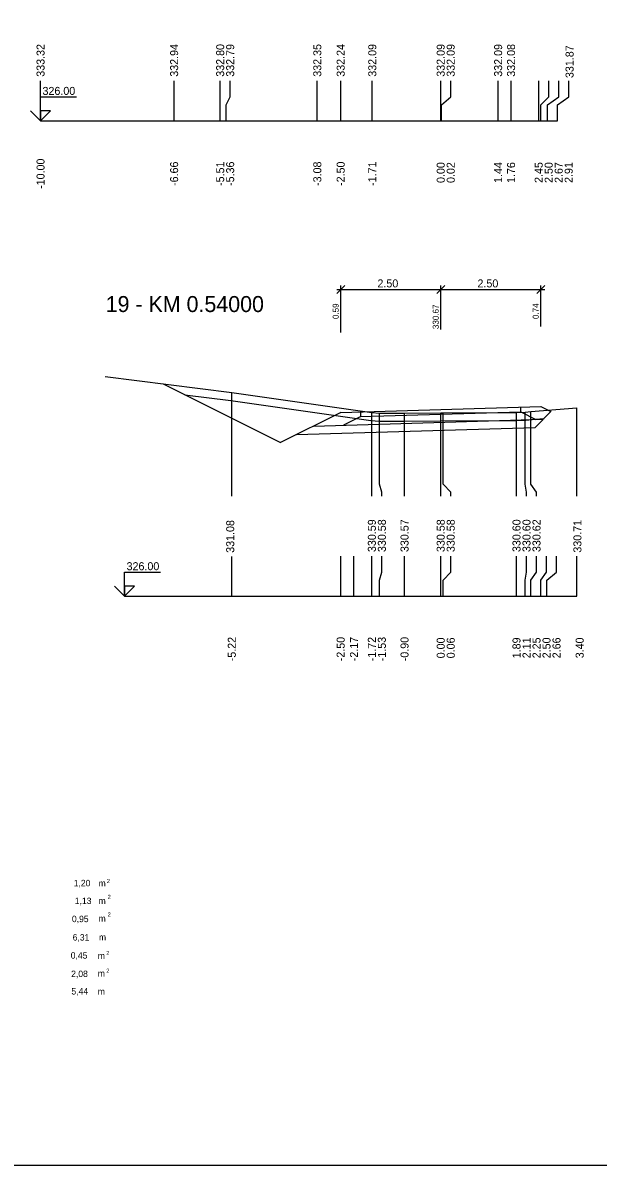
# Model space of a CAD drawing. Extents: x 1989 to 2511, y -2653 to -2294.
# Drawn here: x 2046.5 to 2060.88, y -2360.13 to -2331.57 of the extents above; entities that cross this region are included whole.
import ezdxf

# ---------------------------------------------------------------- set-up
doc = ezdxf.new("R2010")
doc.units = 0
for name, color, linetype in [('KOTA', 7, 'Continuous'), ('KOTA_DELKY', 7, 'Continuous'), ('KOTA_DELKY_CONT', 7, 'Continuous'), ('REZY_PF_PUVODNI', 7, 'Continuous'), ('SESTAVY_REZU_PF', 7, 'Continuous'), ('SVK', 7, 'Continuous'), ('u_kubatury', 7, 'Continuous'), ('u_sejmuti', 7, 'Continuous'), ('vzorák', 7, 'Continuous'), ('x_rozpiska', 7, 'Continuous')]:
    doc.layers.add(name, color=color, linetype=linetype)

msp = doc.modelspace()

# ---------------------------------------------------------------- linework, layer by layer
at = {"layer": 'KOTA'}
for points in [[(2046.941, -2334.022), (2046.691, -2333.772), (2046.941, -2334.022), (2046.941, -2333.422), (2047.841, -2333.422)], [(2046.941, -2334.022), (2047.191, -2333.772), (2046.941, -2333.772), (2046.941, -2334.022)], [(2046.941, -2334.022), (2047.191, -2333.772), (2046.941, -2333.772)], [(2049.042, -2345.904), (2048.792, -2345.654), (2049.042, -2345.904), (2049.042, -2345.304), (2049.942, -2345.304)], [(2049.042, -2345.904), (2049.292, -2345.654), (2049.042, -2345.654), (2049.042, -2345.904)], [(2049.042, -2345.904), (2049.292, -2345.654), (2049.042, -2345.654)]]:
    msp.add_lwpolyline(points, dxfattribs=at)
at = {"layer": 'KOTA_DELKY'}
for points in [[(2054.341, -2338.334), (2054.541, -2338.134)], [(2054.341, -2338.234), (2057.041, -2338.234)], [(2054.441, -2339.309), (2054.441, -2338.134)], [(2056.841, -2338.334), (2057.041, -2338.134)], [(2056.841, -2338.334), (2057.041, -2338.134)], [(2056.841, -2338.234), (2059.541, -2338.234)], [(2056.941, -2339.234), (2056.941, -2338.134)], [(2056.941, -2339.234), (2056.941, -2338.134)], [(2059.341, -2338.334), (2059.541, -2338.134)], [(2059.441, -2339.159), (2059.441, -2338.134)]]:
    msp.add_lwpolyline(points, dxfattribs=at)
at = {"layer": 'REZY_PF_PUVODNI'}
for points in [[(2048.555, -2340.413), (2051.72, -2340.815), (2055.22, -2341.315)], [(2055.22, -2341.315), (2055.41, -2341.327), (2056.037, -2341.329), (2056.941, -2341.322), (2056.941, -2341.322), (2057, -2341.322), (2058.835, -2341.308), (2059.053, -2341.305), (2059.189, -2341.284)]]:
    msp.add_lwpolyline(points, dxfattribs=at)
at = {"layer": 'SESTAVY_REZU_PF'}
msp.add_line((2059.189, -2341.284), (2060.341, -2341.194), dxfattribs=at)
for points in [[(2046.941, -2334.022), (2059.856, -2334.022)], [(2049.042, -2345.904), (2060.341, -2345.904)]]:
    msp.add_lwpolyline(points, dxfattribs=at)
at = {"layer": 'SVK'}
for p, q in [((2060.341, -2343.404), (2060.341, -2341.194)), ((2060.341, -2345.904), (2060.341, -2344.904))]:
    msp.add_line(p, q, dxfattribs=at)
for points in [[(2046.941, -2334.022), (2046.941, -2333.022)], [(2046.941, -2334.022), (2046.941, -2333.022)], [(2050.279, -2334.022), (2050.279, -2333.022)], [(2051.43, -2334.022), (2051.43, -2333.022)], [(2051.581, -2334.022), (2051.581, -2333.622), (2051.68, -2333.422), (2051.68, -2333.022)], [(2053.857, -2334.022), (2053.857, -2333.022)], [(2054.441, -2334.022), (2054.441, -2333.022)], [(2055.231, -2334.022), (2055.231, -2333.022)], [(2056.941, -2334.022), (2056.941, -2333.022)], [(2056.96, -2334.022), (2056.96, -2333.622), (2057.191, -2333.422), (2057.191, -2333.022)], [(2058.376, -2334.022), (2058.376, -2333.022)], [(2058.699, -2334.022), (2058.699, -2333.022)], [(2059.389, -2334.022), (2059.389, -2333.022)], [(2059.441, -2334.022), (2059.441, -2333.622), (2059.639, -2333.422), (2059.639, -2333.022)], [(2059.613, -2334.022), (2059.613, -2333.622), (2059.889, -2333.422), (2059.889, -2333.022)], [(2059.856, -2334.022), (2059.856, -2333.622), (2060.139, -2333.422), (2060.139, -2333.022)], [(2051.72, -2343.405), (2051.72, -2340.815)], [(2055.22, -2343.404), (2055.22, -2341.315)], [(2055.47, -2343.404), (2055.47, -2343.304), (2055.41, -2343.104), (2055.41, -2341.327)], [(2056.037, -2343.404), (2056.037, -2341.329)], [(2056.941, -2343.404), (2056.941, -2341.322)], [(2057.191, -2343.404), (2057.191, -2343.304), (2057, -2343.104), (2057, -2341.322)], [(2058.835, -2343.404), (2058.835, -2341.308)], [(2059.085, -2343.404), (2059.085, -2343.304), (2059.053, -2343.104), (2059.053, -2341.305)], [(2059.335, -2343.404), (2059.335, -2343.304), (2059.189, -2343.104), (2059.189, -2341.284)], [(2051.72, -2345.904), (2051.72, -2344.912)], [(2054.441, -2345.904), (2054.441, -2344.904)], [(2054.774, -2345.904), (2054.774, -2344.904)], [(2055.22, -2345.904), (2055.22, -2344.904)], [(2055.41, -2345.904), (2055.41, -2345.504), (2055.47, -2345.304), (2055.47, -2344.904)], [(2056.037, -2345.904), (2056.037, -2344.904)], [(2056.941, -2345.904), (2056.941, -2344.904)], [(2057, -2345.904), (2057, -2345.504), (2057.191, -2345.304), (2057.191, -2344.904)], [(2058.835, -2345.904), (2058.835, -2344.904)], [(2059.053, -2345.904), (2059.053, -2345.504), (2059.085, -2345.304), (2059.085, -2344.904)], [(2059.189, -2345.904), (2059.189, -2345.504), (2059.335, -2345.304), (2059.335, -2344.904)], [(2059.441, -2345.904), (2059.441, -2345.504), (2059.585, -2345.304), (2059.585, -2344.904)], [(2059.596, -2345.904), (2059.596, -2345.504), (2059.835, -2345.304), (2059.835, -2344.904)]]:
    msp.add_lwpolyline(points, dxfattribs=at)
at = {"layer": 'u_sejmuti'}
msp.add_line((2059.205, -2341.483), (2059.523, -2341.459), dxfattribs=at)
for points in [[(2050.544, -2340.867), (2051.693, -2341.014), (2055.192, -2341.513)], [(2055.207, -2341.515), (2055.403, -2341.527), (2056.037, -2341.529), (2056.942, -2341.522), (2058.837, -2341.508), (2059.069, -2341.505), (2059.219, -2341.482)]]:
    msp.add_lwpolyline(points, dxfattribs=at)
at = {"layer": 'vzorák'}
for p, q in [((2050.003, -2340.597), (2052.934, -2342.062)), ((2054.441, -2341.309), (2059.441, -2341.159)), ((2058.941, -2341.294), (2058.941, -2341.174)), ((2059.441, -2341.159), (2059.695, -2341.286)), ((2054.441, -2341.309), (2052.934, -2342.062)), ((2053.759, -2341.649), (2059.504, -2341.477)), ((2054.941, -2341.414), (2054.515, -2341.627)), ((2054.941, -2341.414), (2058.941, -2341.294)), ((2054.941, -2341.414), (2054.941, -2341.294)), ((2058.941, -2341.294), (2059.318, -2341.483)), ((2059.298, -2341.683), (2059.695, -2341.286)), ((2053.334, -2341.862), (2059.298, -2341.683))]:
    msp.add_line(p, q, dxfattribs=at)
at = {"layer": 'x_rozpiska'}
msp.add_lwpolyline([(2078.309, -2300.726), (1994.309, -2300.726), (1994.309, -2360.126), (2078.309, -2360.126)], close=True, dxfattribs=at)

# ---------------------------------------------------------------- texts
at = {"layer": 'KOTA'}
for p in [(2046.99, -2333.372), (2049.091, -2345.254)]:
    msp.add_text('326.00', height=0.2, dxfattribs=at).set_placement(p)
at = {"layer": 'KOTA_DELKY'}
for p in [(2055.36, -2338.184), (2057.86, -2338.184)]:
    msp.add_text('2.50', height=0.2, dxfattribs=at).set_placement(p)
at = {"layer": 'KOTA_DELKY_CONT'}
for s, p in [('0.59', (2054.391, -2338.975)), ('330.67', (2056.891, -2339.226)), ('0.74', (2059.391, -2338.975))]:
    msp.add_text(s, height=0.15, rotation=90, dxfattribs=at).set_placement(p)
at = {"layer": 'SESTAVY_REZU_PF'}
msp.add_text('19 - KM 0.54000', height=0.4, dxfattribs=at).set_placement((2048.569, -2338.8))
at = {"layer": 'SVK'}
for s, p in [(' 333.32', (2047.041, -2332.992)), (' 332.94', (2050.379, -2332.992)), (' 332.80', (2051.53, -2332.992)), (' 332.79', (2051.78, -2332.992)), (' 332.35', (2053.957, -2332.992)), (' 332.24', (2054.541, -2332.992)), (' 332.09', (2055.331, -2332.992)), (' 332.09', (2057.041, -2332.992)), (' 332.09', (2057.291, -2332.992)), (' 332.09', (2058.476, -2332.992)), (' 332.08', (2058.799, -2332.992)), (' 331.87', (2060.261, -2333.025)), ('-10.00', (2047.041, -2335.722)), (' -6.66', (2050.379, -2335.722)), (' -5.51', (2051.53, -2335.722)), (' -5.36', (2051.78, -2335.722)), (' -3.08', (2053.957, -2335.722)), (' -2.50', (2054.541, -2335.722)), (' -1.71', (2055.331, -2335.722)), ('  0.00', (2057.041, -2335.722)), ('  0.02', (2057.291, -2335.722)), ('  1.44', (2058.476, -2335.722)), ('  1.76', (2058.799, -2335.722)), ('  2.45', (2059.489, -2335.722)), ('  2.50', (2059.739, -2335.722)), ('  2.67', (2059.989, -2335.722)), ('  2.91', (2060.239, -2335.722)), (' 331.08', (2051.781, -2344.893)), (' 330.59', (2055.32, -2344.874)), (' 330.58', (2055.57, -2344.874)), (' 330.57', (2056.137, -2344.874)), (' 330.58', (2057.041, -2344.874)), (' 330.58', (2057.291, -2344.874)), (' 330.60', (2058.935, -2344.874)), (' 330.60', (2059.185, -2344.874)), (' 330.62', (2059.435, -2344.874)), (' 330.71', (2060.457, -2344.889)), (' -5.22', (2051.82, -2347.604)), (' -2.50', (2054.541, -2347.604)), (' -2.17', (2054.874, -2347.604)), (' -1.72', (2055.32, -2347.604)), (' -1.53', (2055.57, -2347.604)), (' -0.90', (2056.137, -2347.604)), ('  0.00', (2057.041, -2347.604)), ('  0.06', (2057.291, -2347.604)), ('  1.89', (2058.935, -2347.604)), ('  2.11', (2059.185, -2347.604)), ('  2.25', (2059.435, -2347.604)), ('  2.50', (2059.685, -2347.604)), ('  2.66', (2059.935, -2347.604)), ('  3.40', (2060.513, -2347.604))]:
    msp.add_text(s, height=0.2, rotation=90, dxfattribs=at).set_placement(p)
at = {"layer": 'u_kubatury'}
for s, height, p in [('2', 0.104, (2048.595, -2353.075)), ('1,20', 0.16, (2047.77, -2353.154)), ('m', 0.16, (2048.392, -2353.159)), ('1,13', 0.16, (2047.797, -2353.599)), ('m', 0.16, (2048.392, -2353.596)), ('2', 0.104, (2048.617, -2353.472)), ('2', 0.104, (2048.617, -2353.914)), ('0,95', 0.16, (2047.725, -2354.051)), ('m', 0.16, (2048.392, -2354.039)), ('6,31', 0.16, (2047.744, -2354.511)), ('m', 0.16, (2048.4, -2354.508)), ('0,45', 0.16, (2047.695, -2354.963)), ('m', 0.16, (2048.371, -2354.969)), ('2', 0.104, (2048.582, -2354.876)), ('2', 0.104, (2048.582, -2355.318)), ('2,08', 0.16, (2047.706, -2355.423)), ('m', 0.16, (2048.371, -2355.411)), ('5,44', 0.16, (2047.713, -2355.86)), ('m', 0.16, (2048.371, -2355.865))]:
    msp.add_text(s, height=height, dxfattribs=at).set_placement(p)

doc.saveas('drawing.dxf')
